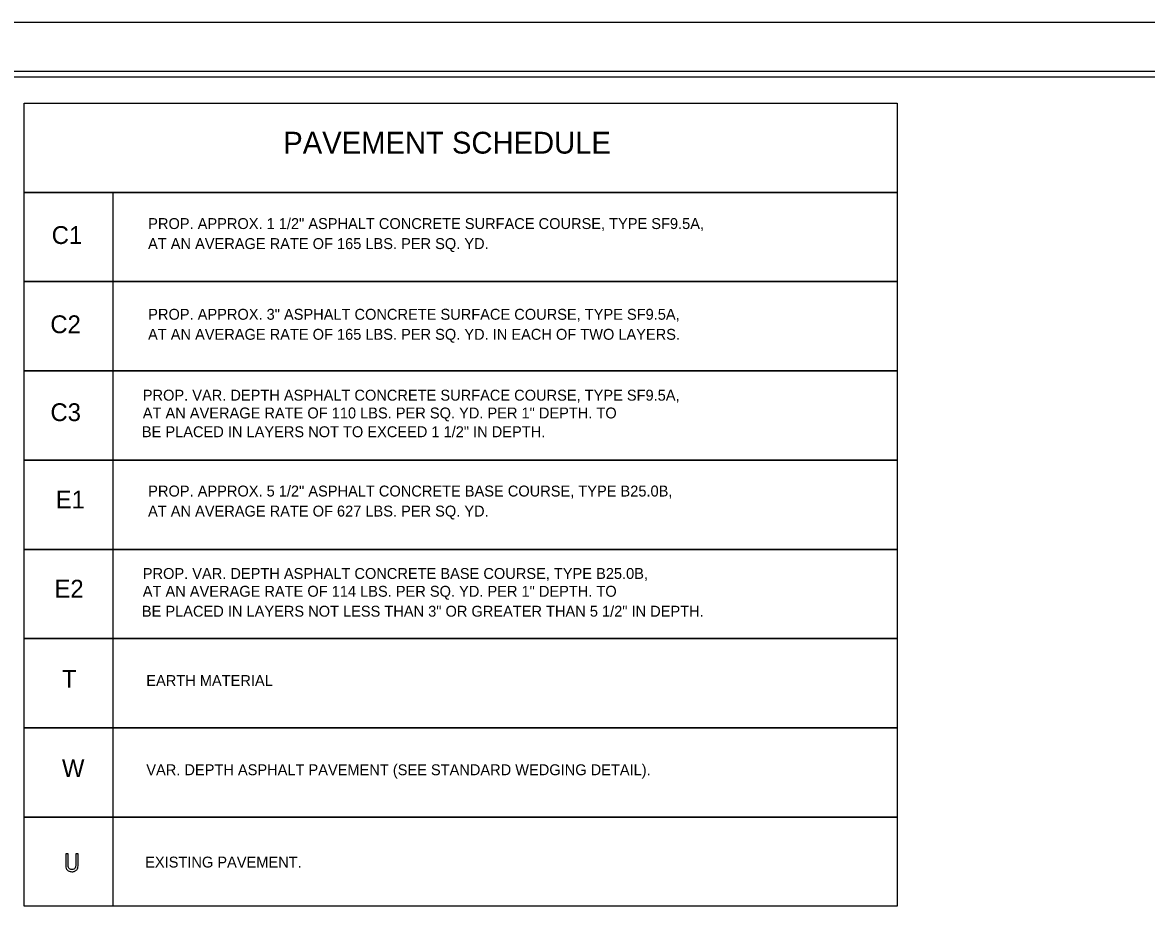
# Model space of a CAD drawing. Extents: x 55823 to 57507, y 47399 to 48499.
# Drawn here: x 56415 to 56930, y 48093 to 48499 of the extents above; entities that cross this region are included whole.
import ezdxf

# ---------------------------------------------------------------- set-up
doc = ezdxf.new("R2010")
doc.units = 0
for name, color, linetype in [('Prop Pavement Schedule Description CELL', 7, 'Continuous'), ('Sheet Plot Border Inside CELL', 7, 'Continuous'), ('Sheet Plot Border Outside CELL', 7, 'Continuous'), ('Sheet Typical CELL', 7, 'Continuous')]:
    doc.layers.add(name, color=color, linetype=linetype)

msp = doc.modelspace()

# ---------------------------------------------------------------- linework, layer by layer
at = {"layer": 'Prop Pavement Schedule Description CELL'}
for p, q in [((56415.65, 48257.83), (56415.65, 48298.74)), ((56415.65, 48298.74), (56815.65, 48298.74)), ((56456.56, 48257.83), (56456.56, 48298.74)), ((56815.65, 48298.74), (56815.65, 48257.83)), ((56456.56, 48257.83), (56415.65, 48257.83)), ((56815.65, 48257.83), (56456.56, 48257.83)), ((56456.56, 48216.92), (56415.65, 48216.92)), ((56815.65, 48216.92), (56456.56, 48216.92)), ((56456.56, 48176.02), (56415.65, 48176.02)), ((56815.65, 48176.02), (56456.56, 48176.02)), ((56415.65, 48094.2), (56415.65, 48094.2))]:
    msp.add_line(p, q, dxfattribs=at)
for points in [[(56415.65, 48462.39), (56815.65, 48462.39), (56815.65, 48421.48), (56415.65, 48421.48)], [(56434.73, 48113.33), (56434.75, 48112.69), (56434.83, 48112.12), (56435, 48111.56), (56435.13, 48111.3), (56435.29, 48111.06), (56435.58, 48110.72), (56435.94, 48110.46), (56436.34, 48110.26), (56436.77, 48110.14), (56437.16, 48110.09), (56437.55, 48110.07), (56437.94, 48110.08), (56438.33, 48110.12), (56438.61, 48110.18), (56438.89, 48110.27), (56439.15, 48110.4), (56439.4, 48110.55), (56439.61, 48110.74), (56439.81, 48110.94), (56439.97, 48111.18), (56440.11, 48111.43), (56440.25, 48111.8), (56440.35, 48112.18), (56440.43, 48112.75), (56440.45, 48113.33), (56440.45, 48118.29), (56439.34, 48118.29), (56439.34, 48113.26), (56439.33, 48112.83), (56439.27, 48112.43), (56439.16, 48112.03), (56438.99, 48111.7), (56438.74, 48111.41), (56438.41, 48111.2), (56438.05, 48111.08), (56437.59, 48111.03), (56437.14, 48111.07), (56436.76, 48111.2), (56436.43, 48111.42), (56436.17, 48111.71), (56435.99, 48112.06), (56435.88, 48112.5), (56435.84, 48112.88), (56435.84, 48113.26), (56435.84, 48118.29), (56434.73, 48118.29)]]:
    msp.add_lwpolyline(points, close=True, dxfattribs=at)
for points in [[(56456.56, 48380.57), (56415.65, 48380.57), (56415.65, 48421.48), (56815.65, 48421.48), (56815.65, 48380.57), (56456.56, 48380.57), (56456.56, 48421.48)], [(56456.56, 48339.65), (56415.65, 48339.65), (56415.65, 48380.57), (56815.65, 48380.57), (56815.65, 48339.65), (56456.56, 48339.65), (56456.56, 48380.57)], [(56456.56, 48298.74), (56415.65, 48298.74), (56415.65, 48339.65), (56815.65, 48339.65), (56815.65, 48298.74), (56456.56, 48298.74), (56456.56, 48339.65)], [(56456.56, 48216.92), (56415.65, 48216.92), (56415.65, 48257.83), (56815.65, 48257.83), (56815.65, 48216.92), (56456.56, 48216.92), (56456.56, 48257.83)], [(56456.56, 48176.02), (56415.65, 48176.02), (56415.65, 48216.92), (56815.65, 48216.92), (56815.65, 48176.02), (56456.56, 48176.02), (56456.56, 48216.92)], [(56456.56, 48135.11), (56415.65, 48135.11), (56415.65, 48176.02), (56815.65, 48176.02), (56815.65, 48135.11), (56456.56, 48135.11), (56456.56, 48176.02)], [(56456.56, 48094.2), (56415.65, 48094.2), (56415.65, 48135.11), (56815.65, 48135.11), (56815.65, 48094.2), (56456.56, 48094.2), (56456.56, 48135.11)]]:
    msp.add_lwpolyline(points, dxfattribs=at)
at = {"layer": 'Sheet Plot Border Inside CELL'}
msp.add_lwpolyline([(57502.66, 48476.93), (55836.16, 48476.93), (55836.16, 47421.83), (57502.66, 47421.83)], close=True, dxfattribs=at)
at = {"layer": 'Sheet Plot Border Outside CELL'}
msp.add_lwpolyline([(57507.16, 48499.38), (55823.16, 48499.38), (55823.16, 47399.38), (57507.16, 47399.38)], close=True, dxfattribs=at)
at = {"layer": 'Sheet Typical CELL'}
msp.add_lwpolyline([(57490.16, 48474.38), (55990.16, 48474.38), (55990.16, 47424.38), (57490.16, 47424.38)], close=True, dxfattribs=at)

# ---------------------------------------------------------------- texts
at = {"layer": 'Prop Pavement Schedule Description CELL'}
for s, height, p in [('PAVEMENT SCHEDULE', 10, (56534.43, 48439.27)), ('C1', 8.167, (56428.33, 48397.84)), ('PROP. APPROX. 1 1/2" ASPHALT CONCRETE SURFACE COURSE, TYPE SF9.5A,', 5, (56472.55, 48404.69)), ('AT AN AVERAGE RATE OF 165 LBS. PER SQ. YD.', 5, (56472.47, 48395.51)), ('C2', 8.167, (56427.71, 48356.94)), ('PROP. APPROX. 3" ASPHALT CONCRETE SURFACE COURSE, TYPE SF9.5A,', 5, (56472.55, 48363.1)), ('AT AN AVERAGE RATE OF 165 LBS. PER SQ. YD. IN EACH OF TWO LAYERS.', 5, (56472.47, 48353.92)), ('PROP. VAR. DEPTH ASPHALT CONCRETE SURFACE COURSE, TYPE SF9.5A,', 5, (56470.06, 48326.02)), ('C3', 8.167, (56427.76, 48316.64)), ('AT AN AVERAGE RATE OF 110 LBS. PER SQ. YD. PER 1" DEPTH. TO', 5, (56470.06, 48317.86)), ('BE PLACED IN LAYERS NOT TO EXCEED 1 1/2" IN DEPTH.', 5, (56469.65, 48309.26)), ('PROP. APPROX. 5 1/2" ASPHALT CONCRETE BASE COURSE, TYPE B25.0B,', 5, (56472.55, 48282.07)), ('E1', 8.167, (56430.17, 48276.6)), ('AT AN AVERAGE RATE OF 627 LBS. PER SQ. YD.', 5, (56472.47, 48272.89)), ('PROP. VAR. DEPTH ASPHALT CONCRETE BASE COURSE, TYPE B25.0B,', 5, (56470.06, 48244.28)), ('E2', 8.167, (56429.6, 48235.73)), ('AT AN AVERAGE RATE OF 114 LBS. PER SQ. YD. PER 1" DEPTH. TO', 5, (56470.06, 48236.12)), ('BE PLACED IN LAYERS NOT LESS THAN 3" OR GREATER THAN 5 1/2" IN DEPTH.', 5, (56469.65, 48226.98)), ('T', 8.17, (56433.03, 48194.38)), ('EARTH MATERIAL', 5, (56471.67, 48195.21)), ('W', 8.17, (56433.02, 48153.48)), ('VAR. DEPTH ASPHALT PAVEMENT (SEE STANDARD WEDGING DETAIL).', 5, (56471.67, 48154.3)), ('EXISTING PAVEMENT.', 5, (56471.15, 48111.98))]:
    msp.add_text(s, height=height, dxfattribs=at).set_placement(p)

doc.saveas('drawing.dxf')
